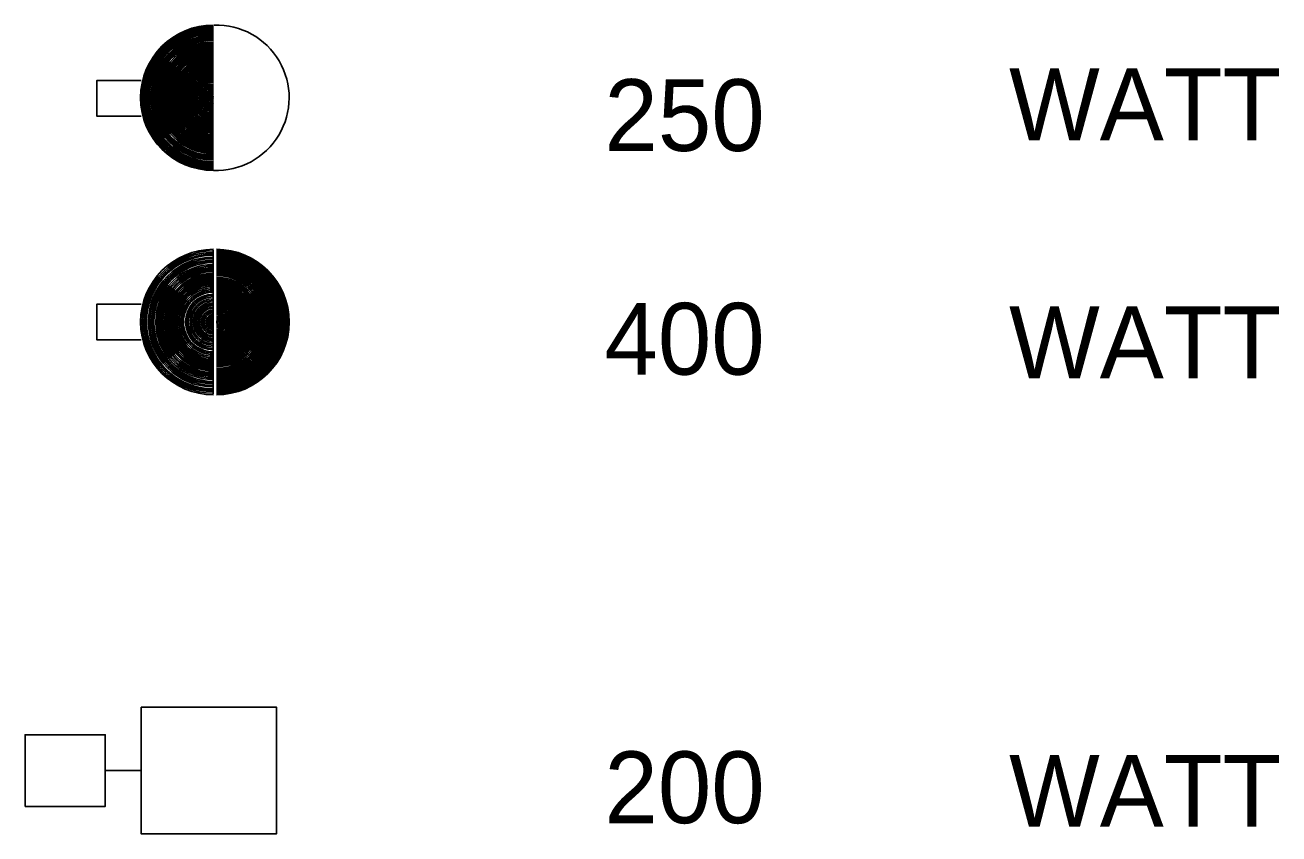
# Model space of a CAD drawing. Extents: x 10019.5 to 10026.1, y 9984.8 to 9994.8.
# Drawn here: x 10019.575 to 10020.622, y 9991.025 to 9991.701 of the extents above; entities that cross this region are included whole.
import ezdxf

# ---------------------------------------------------------------- set-up
doc = ezdxf.new("R2010")
doc.units = 0
doc.layers.add('DETL-LINE', color=7, linetype='Continuous')
doc.layers.add('DETL-NOTE', color=7, linetype='Continuous')

msp = doc.modelspace()

# ---------------------------------------------------------------- linework, layer by layer
at = {"layer": 'DETL-LINE'}
for p, q in [((10019.732, 9991.5127), (10019.732, 9991.3927)), ((10019.732, 9991.5127), (10019.732, 9991.3927)), ((10019.672, 9991.0777), (10019.642, 9991.0777))]:
    msp.add_line(p, q, dxfattribs=at)
for points in [[(10019.672, 9991.6247), (10019.635, 9991.6247), (10019.635, 9991.6547), (10019.672, 9991.6547)], [(10019.672, 9991.4377), (10019.635, 9991.4377), (10019.635, 9991.4677), (10019.672, 9991.4677)]]:
    msp.add_lwpolyline(points, dxfattribs=at)
for points in [[(10019.672, 9991.1307), (10019.785, 9991.1307), (10019.785, 9991.0247), (10019.672, 9991.0247)], [(10019.575, 9991.0477), (10019.642, 9991.0477), (10019.642, 9991.1077), (10019.575, 9991.1077)]]:
    msp.add_lwpolyline(points, close=True, dxfattribs=at)
for centre, radius, start, end in [((10019.7323, 9991.6402), 0.0608, 90, 270), ((10019.7323, 9991.6402), 0.0599, 90, 270), ((10019.7323, 9991.6402), 0.059, 90, 270), ((10019.7323, 9991.6402), 0.0582, 90, 270), ((10019.7323, 9991.6402), 0.0575, 90, 270), ((10019.7323, 9991.6402), 0.0567, 90, 270), ((10019.7323, 9991.6402), 0.0559, 90, 270), ((10019.7323, 9991.6402), 0.055, 90, 270), ((10019.7323, 9991.6402), 0.0543, 90, 270), ((10019.7323, 9991.6402), 0.0535, 90, 270), ((10019.7323, 9991.6402), 0.0522, 90, 270), ((10019.7323, 9991.6402), 0.0517, 90, 270), ((10019.7348, 9991.6402), 0.0608, 267.8132, 91.649), ((10019.7323, 9991.6402), 0.0508, 90, 270), ((10019.7323, 9991.6402), 0.0501, 90, 270), ((10019.7323, 9991.6402), 0.0497, 90, 270), ((10019.7323, 9991.6402), 0.049, 90, 270), ((10019.7323, 9991.6402), 0.0481, 90, 270), ((10019.7323, 9991.6402), 0.0468, 90, 270), ((10019.7323, 9991.6402), 0.0456, 90, 270), ((10019.7323, 9991.6402), 0.045, 90, 270), ((10019.7323, 9991.6402), 0.0442, 90, 270), ((10019.7323, 9991.6402), 0.0434, 90, 270), ((10019.7323, 9991.6402), 0.0426, 90, 270), ((10019.7323, 9991.6402), 0.0418, 90, 270), ((10019.7323, 9991.6402), 0.0409, 90, 270), ((10019.7323, 9991.6402), 0.0399, 90, 270), ((10019.7323, 9991.6402), 0.0391, 90, 270), ((10019.7323, 9991.6402), 0.0384, 90, 270), ((10019.7323, 9991.6402), 0.0381, 90, 270), ((10019.7323, 9991.6402), 0.0376, 90, 270), ((10019.7323, 9991.6402), 0.0367, 90, 270), ((10019.7323, 9991.6402), 0.0359, 90, 270), ((10019.7323, 9991.6402), 0.0357, 90, 270), ((10019.7323, 9991.6402), 0.0346, 90, 270), ((10019.7323, 9991.6402), 0.0336, 90, 270), ((10019.7323, 9991.6402), 0.0331, 90, 270), ((10019.7323, 9991.6402), 0.0325, 90, 270), ((10019.7323, 9991.6402), 0.0319, 90, 270), ((10019.7323, 9991.6402), 0.0313, 90, 270), ((10019.7323, 9991.6402), 0.0305, 90, 270), ((10019.7323, 9991.6402), 0.0293, 90, 270), ((10019.7323, 9991.6402), 0.0286, 90, 270), ((10019.7323, 9991.6402), 0.0283, 90, 270), ((10019.7323, 9991.6402), 0.0275, 90, 270), ((10019.7323, 9991.6402), 0.0269, 90, 270), ((10019.7323, 9991.6402), 0.026, 90, 270), ((10019.7323, 9991.6402), 0.0255, 90, 270), ((10019.7323, 9991.6402), 0.0247, 90, 270), ((10019.7323, 9991.6402), 0.0237, 90, 270), ((10019.7323, 9991.6402), 0.0233, 90, 270), ((10019.7323, 9991.6402), 0.0223, 90, 270), ((10019.7323, 9991.6402), 0.0212, 90, 270), ((10019.7323, 9991.6402), 0.0206, 90, 270), ((10019.7323, 9991.6402), 0.0195, 90, 270), ((10019.7323, 9991.6402), 0.0184, 90, 270), ((10019.7323, 9991.6402), 0.0175, 90, 270), ((10019.7323, 9991.6402), 0.0168, 90, 270), ((10019.7323, 9991.6402), 0.0161, 90, 270), ((10019.7323, 9991.6402), 0.0153, 90, 270), ((10019.7323, 9991.6402), 0.0148, 90, 270), ((10019.7323, 9991.6402), 0.0141, 90, 270), ((10019.7323, 9991.6402), 0.013, 90, 270), ((10019.7323, 9991.6402), 0.0116, 90, 270), ((10019.7323, 9991.6402), 0.0111, 90, 270), ((10019.7323, 9991.6402), 0.0102, 90, 270), ((10019.7323, 9991.6402), 0.00947, 90, 270), ((10019.7323, 9991.6402), 0.0089, 90, 270), ((10019.7323, 9991.6402), 0.00816, 90, 270), ((10019.7323, 9991.6402), 0.00711, 90, 270), ((10019.7323, 9991.6402), 0.00629, 90, 270), ((10019.7323, 9991.6402), 0.00582, 90, 270), ((10019.7323, 9991.6402), 0.00503, 90, 270), ((10019.7323, 9991.6402), 0.00391, 90, 270), ((10019.7323, 9991.6402), 0.00322, 90, 270), ((10019.7323, 9991.6402), 0.00263, 90, 270), ((10019.7323, 9991.6402), 0.00158, 90, 270), ((10019.7323, 9991.6402), 0.00121, 90, 270), ((10019.7323, 9991.6402), 0.000463, 90, 270), ((10019.7323, 9991.6402), 0.000463, 90, 270), ((10019.7323, 9991.4527), 0.0608, 90, 270), ((10019.7348, 9991.4527), 0.0608, 270, 90), ((10019.7323, 9991.4527), 0.0595, 90, 270), ((10019.7323, 9991.4527), 0.0582, 90, 270), ((10019.7323, 9991.4527), 0.0569, 90, 270), ((10019.7323, 9991.4527), 0.0559, 90, 270), ((10019.7323, 9991.4527), 0.0543, 90, 270), ((10019.7323, 9991.4527), 0.053, 90, 270), ((10019.7323, 9991.4527), 0.0517, 90, 270), ((10019.7323, 9991.4527), 0.0509, 90, 270), ((10019.7348, 9991.4527), 0.06, 270, 90), ((10019.7348, 9991.4527), 0.0593, 270, 90), ((10019.7348, 9991.4527), 0.0588, 270, 90), ((10019.7348, 9991.4527), 0.0582, 270, 90), ((10019.7348, 9991.4527), 0.0575, 270, 90), ((10019.7348, 9991.4527), 0.057, 270, 90), ((10019.7348, 9991.4527), 0.0562, 270, 90), ((10019.7348, 9991.4527), 0.0555, 270, 90), ((10019.7348, 9991.4527), 0.0545, 270, 90), ((10019.7348, 9991.4527), 0.0538, 270, 90), ((10019.7348, 9991.4527), 0.053, 270, 90), ((10019.7348, 9991.4527), 0.0528, 270, 90), ((10019.7348, 9991.4527), 0.052, 270, 90), ((10019.7348, 9991.4527), 0.0515, 270, 90), ((10019.7348, 9991.4527), 0.051, 270, 90), ((10019.7348, 9991.4527), 0.0503, 270, 90), ((10019.7323, 9991.4527), 0.0497, 90, 270), ((10019.7323, 9991.4527), 0.0481, 90, 270), ((10019.7323, 9991.4527), 0.0468, 90, 270), ((10019.7323, 9991.4527), 0.0456, 90, 270), ((10019.7323, 9991.4527), 0.0444, 90, 270), ((10019.7323, 9991.4527), 0.0434, 90, 270), ((10019.7323, 9991.4527), 0.0423, 90, 270), ((10019.7323, 9991.4527), 0.0409, 90, 270), ((10019.7323, 9991.4527), 0.04, 90, 270), ((10019.7348, 9991.4527), 0.0495, 270, 90), ((10019.7348, 9991.4527), 0.0488, 270, 90), ((10019.7348, 9991.4527), 0.048, 270, 90), ((10019.7348, 9991.4527), 0.0476, 270, 90), ((10019.7348, 9991.4527), 0.0471, 270, 90), ((10019.7348, 9991.4527), 0.0463, 270, 90), ((10019.7348, 9991.4527), 0.0456, 270, 90), ((10019.7348, 9991.4527), 0.0449, 270, 90), ((10019.7348, 9991.4527), 0.0442, 270, 90), ((10019.7348, 9991.4527), 0.0433, 270, 90), ((10019.7348, 9991.4527), 0.0426, 270, 90), ((10019.7348, 9991.4527), 0.0417, 270, 90), ((10019.7348, 9991.4527), 0.0408, 270, 90), ((10019.7348, 9991.4527), 0.0398, 270, 90), ((10019.7323, 9991.4527), 0.0391, 90, 270), ((10019.7323, 9991.4527), 0.0381, 90, 270), ((10019.7323, 9991.4527), 0.037, 90, 270), ((10019.7323, 9991.4527), 0.0359, 90, 270), ((10019.7323, 9991.4527), 0.0349, 90, 270), ((10019.7323, 9991.4527), 0.034, 90, 270), ((10019.7323, 9991.4527), 0.0331, 90, 270), ((10019.7323, 9991.4527), 0.0322, 90, 270), ((10019.7323, 9991.4527), 0.0313, 90, 270), ((10019.7323, 9991.4527), 0.03, 90, 270), ((10019.7348, 9991.4527), 0.0389, 270, 90), ((10019.7348, 9991.4527), 0.0375, 270, 90), ((10019.7348, 9991.4527), 0.0364, 270, 90), ((10019.7348, 9991.4527), 0.0354, 270, 90), ((10019.7348, 9991.4527), 0.0345, 270, 90), ((10019.7348, 9991.4527), 0.0337, 270, 90), ((10019.7348, 9991.4527), 0.0327, 270, 90), ((10019.7348, 9991.4527), 0.0318, 270, 90), ((10019.7348, 9991.4527), 0.0309, 270, 90), ((10019.7348, 9991.4527), 0.0302, 270, 90), ((10019.7348, 9991.4527), 0.0294, 270, 90), ((10019.7323, 9991.4527), 0.0286, 90, 270), ((10019.7323, 9991.4527), 0.0272, 90, 270), ((10019.7323, 9991.4527), 0.026, 90, 270), ((10019.7323, 9991.4527), 0.025, 90, 270), ((10019.7323, 9991.4527), 0.0233, 90, 270), ((10019.7323, 9991.4527), 0.0223, 90, 270), ((10019.7323, 9991.4527), 0.021, 90, 270), ((10019.7323, 9991.4527), 0.0195, 90, 270), ((10019.7348, 9991.4527), 0.0284, 270, 90), ((10019.7348, 9991.4527), 0.0274, 270, 90), ((10019.7348, 9991.4527), 0.0272, 270, 90), ((10019.7348, 9991.4527), 0.0264, 270, 90), ((10019.7348, 9991.4527), 0.0259, 270, 90), ((10019.7348, 9991.4527), 0.0253, 270, 90), ((10019.7348, 9991.4527), 0.0243, 270, 90), ((10019.7348, 9991.4527), 0.0235, 270, 90), ((10019.7348, 9991.4527), 0.0229, 270, 90), ((10019.7348, 9991.4527), 0.0224, 270, 90), ((10019.7348, 9991.4527), 0.0213, 270, 90), ((10019.7348, 9991.4527), 0.0203, 270, 90), ((10019.7348, 9991.4527), 0.0198, 270, 90), ((10019.7348, 9991.4527), 0.019, 270, 90), ((10019.7323, 9991.4527), 0.0182, 90, 270), ((10019.7323, 9991.4527), 0.0168, 90, 270), ((10019.7323, 9991.4527), 0.0156, 90, 270), ((10019.7323, 9991.4527), 0.0148, 90, 270), ((10019.7323, 9991.4527), 0.0137, 90, 270), ((10019.7323, 9991.4527), 0.0125, 90, 270), ((10019.7323, 9991.4527), 0.0116, 90, 270), ((10019.7323, 9991.4527), 0.0101, 90, 270), ((10019.7323, 9991.4527), 0.0089, 90, 270), ((10019.7348, 9991.4527), 0.0183, 270, 90), ((10019.7348, 9991.4527), 0.0175, 270, 90), ((10019.7348, 9991.4527), 0.0166, 270, 90), ((10019.7348, 9991.4527), 0.016, 270, 90), ((10019.7348, 9991.4527), 0.0149, 270, 90), ((10019.7348, 9991.4527), 0.0139, 270, 90), ((10019.7348, 9991.4527), 0.0128, 270, 90), ((10019.7348, 9991.4527), 0.0119, 270, 90), ((10019.7348, 9991.4527), 0.0111, 270, 90), ((10019.7348, 9991.4527), 0.0102, 270, 90), ((10019.7348, 9991.4527), 0.00898, 270, 90), ((10019.7323, 9991.4527), 0.0077, 90, 270), ((10019.7323, 9991.4527), 0.00629, 90, 270), ((10019.7323, 9991.4527), 0.00551, 90, 270), ((10019.7323, 9991.4527), 0.0047, 90, 270), ((10019.7323, 9991.4527), 0.00391, 90, 270), ((10019.7323, 9991.4527), 0.00263, 90, 270), ((10019.7323, 9991.4527), 0.00158, 90, 270), ((10019.7323, 9991.4527), 0.000718, 90, 270), ((10019.7323, 9991.4527), 0.00043, 90, 270), ((10019.7348, 9991.4527), 0.00798, 270, 90), ((10019.7348, 9991.4527), 0.00693, 270, 90), ((10019.7348, 9991.4527), 0.00588, 270, 90), ((10019.7348, 9991.4527), 0.00466, 270, 90), ((10019.7348, 9991.4527), 0.00398, 270, 90), ((10019.7348, 9991.4527), 0.00337, 270, 90), ((10019.7348, 9991.4527), 0.00277, 270, 90), ((10019.7348, 9991.4527), 0.00174, 270, 90), ((10019.7348, 9991.4527), 0.00133, 270, 90), ((10019.7348, 9991.4527), 0.000643, 270, 90), ((10019.7348, 9991.4527), 0.000461, 270, 90)]:
    msp.add_arc(centre, radius, start, end, dxfattribs=at)

# ---------------------------------------------------------------- texts
at = {"layer": 'DETL-NOTE'}
for s, p in [('WATT', (10020.397, 9991.6047)), ('250', (10020.059, 9991.5957)), ('400', (10020.059, 9991.4087)), ('WATT', (10020.397, 9991.4057)), ('200', (10020.059, 9991.0337)), ('WATT', (10020.397, 9991.0307))]:
    msp.add_text(s, height=0.06, dxfattribs=at).set_placement(p)

doc.saveas('drawing.dxf')
